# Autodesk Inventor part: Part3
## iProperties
Shininess: 77.0
Length Units: 11269
Angle Units: 11279
Time Units: 11290
Mass Units: 11283
Length Display Precision: 3
Angle Display Precision: 2
Created: 2002-01
Part Number: Part3
Document SubType Name: Modeling
Designer: ***
Density: 0.0
Volumn: 0.0
Area: 0.0
PropertySet Name: Model Information
Control State: 0
Master: False
Checked Out: False
Author: ***
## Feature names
1. Extrusion1
2. Extrusion2
